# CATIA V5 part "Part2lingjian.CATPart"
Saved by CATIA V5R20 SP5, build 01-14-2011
Part number: Part2
Bounding box of the stored display mesh (mm): x -109.499 to 109.497, y -109.499 to 109.499, z -19.843 to 11.864
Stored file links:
  D:\Part2lingjian.CATPart
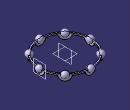
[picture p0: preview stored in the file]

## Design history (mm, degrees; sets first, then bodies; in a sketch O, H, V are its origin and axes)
CircPattern1: of the body so far, instances 8, angular step 45, axis from xy-plane
Body1 (main body)
  Body2
    Sketch1 on xy-plane, origin (0, 0, 0), H (1, 0, 0), V (0, 1, 0)
      circle A1 centre (0, 0) radius 100
      radius A1 = 100
    Pad1: profile Sketch1, direction (0, 0, 1), length 2.5, mirrored extent, thin wall 5
    Sketch2 on xy-plane, origin (0, 0, 0), H (1, 0, 0), V (0, 1, 0)
      arc A1 centre (97.5, 0) radius 20 from (97.5, -20) to (97.5, 20) ccw
      point P1 (97.5, 0)
      construction line L1 (97.5, 0) -> (97.5, -40)
      axis line L2 (97.5, 0) -> (97.5, 30)
      point P4 (97.5, 20)
      point P5 (97.5, -20)
      distance L2 V = 97.5
      coincidence: P1 H, L2 P4, L1 P5
      vertical: L1 V, L2 V
    Shaft1: profile Sketch2, axis Sketch2.L2, angle 360
    Sketch3 on xy-plane, origin (0, 0, 0), H (1, 0, 0), V (0, 1, 0)
      circle A1 centre (0, 0) radius 95
      radius A1 = 95
    Pocket1: profile Sketch3, direction (0, 0, -1), length 60, mirrored extent
    Split1: SplitPlane face of CircPattern1
    Sketch4 on xy-plane, origin (0, 0, 0), H (1, 0, 0), V (0, 1, 0)
      circle A1 centre (0, 0) radius 100
      radius A1 = 100
    Pocket2: profile Sketch4, direction (0, 0, 1), length 60, mirrored extent, outer side
    Plane1: type Offset, RefPlane yz-plane, Offset 97.5
    Sketch5 on Plane1, origin (97.5, 0, 0), H (0, 1, 0), V (0, 0, 1)
      arc A1 centre (0, 0) radius 12 from (12, 0) to (-12, 0) ccw
      construction line L1 (0, 0) -> (30, 0)
      axis line L2 (0, 0) -> (-30, 0)
      point P3 (-12, 0)
      point P4 (12, 0)
      radius A1 = 12
      horizontal: L1 H, L2 H
      coincidence: L2 P3, L1 P4
    Shaft2: profile Sketch5, axis Sketch5.L2, angle 360
    CircPattern2: of Shaft2, instances 8, angular step 45, axis from face of Pocket2
  Assemble1: tool Body2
